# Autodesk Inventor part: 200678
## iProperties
Created: 2007-11
Part Number: 200678
Document SubType Name: Modeling
Designer: JJ
Density: 1.06 g/cm^3
Mass: 15.6401 g
Surface Area: 95.1366 cm^2
Volume: 14.7548 cm^3
Material: ABS Plastic
Description: GEAR HOUSING CASE SIDE 1
Component Category: Lower Component
Author: JJ
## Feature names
1. Extrusion1
2. Extrusion2
3. Extrusion3
4. Extrusion4
5. Extrusion5
6. Extrusion6
7. Revolution1
8. Split1
9. Extrusion7
10. Extrusion8
11. Fillet7
12. Fillet8
13. Fillet9
14. Extrusion9
15. Extrusion11
16. Hole2
17. Chamfer1
18. Fillet13
19. Fillet14
20. Fillet15
21. Fillet16
